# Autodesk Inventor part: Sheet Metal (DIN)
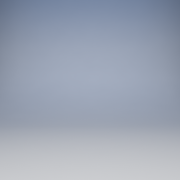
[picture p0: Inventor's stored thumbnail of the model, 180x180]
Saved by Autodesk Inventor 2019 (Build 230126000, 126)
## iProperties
Created: 2018-02
Part Number: Sheet Metal (DIN)
Material: Všeobecné
Document SubType Name: Plech
Density: 1 g/cm^3
Sheet Metal Rule: Výchozí_mm
Appearance: Výchozí
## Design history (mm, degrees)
other parameters: "Tloušťka" = 0.5 (derived), "KSoučinitel" = 4.4, "PoloměrOhybu" = 0.5 (= Tloušťka), "ŠířkaVýštipu" = 0.5 (= Tloušťka), "HloubkaVýštipu" = 0.25 (= 0.5 x Tloušťka), "VelikostRohovéhoVýštipu" = 2 (= 4 x Tloušťka), "MezeraVystřižení" = 0.01, "MinimálníZbytek" = 1 (= 2 x Tloušťka), "PřechodovýPoloměr" = 0.5 (= PoloměrOhybu), "VelikostJacobihoPoloměru" = 0.5 (= PoloměrOhybu), "VelikostMezery" = 0.5 (= Tloušťka)
